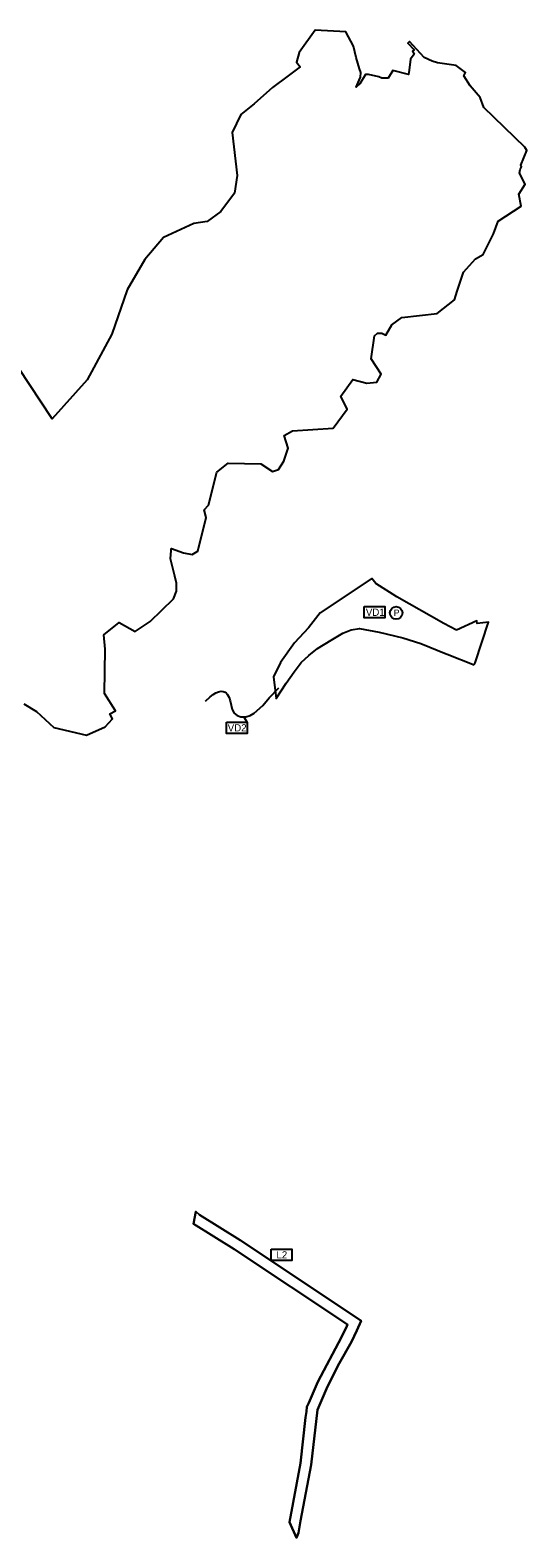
# Model space of a CAD drawing. Extents: x -547623 to -530360, y -1095798 to -1086523.
# Drawn here: x -544764 to -544079, y -1095573 to -1093495 of the extents above; entities that cross this region are included whole.
import ezdxf

# ---------------------------------------------------------------- set-up
doc = ezdxf.new("R2010")
doc.units = 0
for name, color, linetype in [('Vrstva 2', 7, 'Continuous'), ('Vrstva 27', 7, 'Continuous'), ('Vrstva 29', 7, 'Continuous'), ('Vrstva 33', 7, 'Continuous'), ('Vrstva 36', 7, 'Continuous'), ('Vrstva 66', 7, 'Continuous'), ('Vrstva 73', 7, 'Continuous')]:
    doc.layers.add(name, color=color, linetype=linetype)

msp = doc.modelspace()

# ---------------------------------------------------------------- linework, layer by layer
at = {"layer": 'Vrstva 2'}
msp.add_line((-544464.7, -1094448.9), (-544469.2, -1094441.5), dxfattribs=at)
for points in [[(-544303.3, -1094289.4), (-544274.7, -1094289.4), (-544274.7, -1094304.9), (-544303.3, -1094304.9)], [(-544493.3, -1094448.9), (-544464.7, -1094448.9), (-544464.7, -1094464.4), (-544493.3, -1094464.4)]]:
    msp.add_lwpolyline(points, close=True, dxfattribs=at)
at = {"layer": 'Vrstva 27'}
msp.add_lwpolyline([(-544772.6, -1094423.7), (-544755.4, -1094434.1), (-544731.5, -1094456.2), (-544686.3, -1094466.7), (-544660.7, -1094455), (-544650.4, -1094444.2), (-544654, -1094437.3), (-544646.4, -1094433.2), (-544661.7, -1094409.1), (-544660.8, -1094347.9), (-544662.5, -1094328.3), (-544641.1, -1094311.4), (-544619.4, -1094323.8), (-544598.7, -1094310), (-544566.4, -1094278.8), (-544562.2, -1094268.3), (-544562.3, -1094257.2), (-544564.4, -1094247.4), (-544570.5, -1094223.6), (-544569.6, -1094212), (-544569.5, -1094210.6), (-544569.1, -1094209.1), (-544552.5, -1094215.1), (-544540.8, -1094217.7), (-544533.6, -1094213.5), (-544532.8, -1094213.1), (-544521.3, -1094166.5), (-544524, -1094156.1), (-544518.3, -1094149.5), (-544506.4, -1094104.1), (-544491, -1094091.7), (-544446.1, -1094092.6), (-544429.7, -1094103.3), (-544421.7, -1094100.5), (-544414.3, -1094088.9), (-544408.1, -1094071.1), (-544413.8, -1094053.6), (-544402.4, -1094047), (-544346.1, -1094043.3), (-544326.7, -1094017.2), (-544335.8, -1093999.4), (-544319.2, -1093976.5), (-544299.8, -1093981.2), (-544285.8, -1093979.9), (-544280, -1093968.9), (-544293.6, -1093947.9), (-544289.1, -1093916.3), (-544285.1, -1093912.2), (-544279, -1093912.2), (-544273.7, -1093915.3), (-544265.5, -1093900.7), (-544251.4, -1093890.7), (-544202.7, -1093885.2), (-544178.8, -1093866.4), (-544175.4, -1093854.6), (-544166.5, -1093828.2), (-544149.7, -1093810.1), (-544139.3, -1093804.1), (-544125.1, -1093775.4), (-544118.8, -1093757.8), (-544086.8, -1093737.4), (-544090, -1093720.8), (-544081.2, -1093706.9), (-544089, -1093691.9), (-544088.1, -1093686.7), (-544086.5, -1093683.2), (-544087.3, -1093680.9), (-544079.1, -1093660.3), (-544081.8, -1093656), (-544138.2, -1093601.3), (-544143.3, -1093587.3), (-544157.2, -1093571.2), (-544165.8, -1093557.4), (-544163.7, -1093552.9), (-544176.6, -1093543.3), (-544202.3, -1093539.6), (-544209.6, -1093537.3), (-544220.9, -1093532.2), (-544241.1, -1093510.3), (-544243.1, -1093512.6), (-544234.6, -1093521.6), (-544236.7, -1093523.6), (-544234.7, -1093527.8), (-544239.5, -1093534.7), (-544241.4, -1093549.6), (-544242.1, -1093555.6), (-544263.7, -1093550.3), (-544270.3, -1093560.7), (-544279.2, -1093560.9), (-544283.3, -1093558.8), (-544297.5, -1093555.5), (-544301.6, -1093555.8), (-544309.5, -1093568.7), (-544314.3, -1093573.4), (-544310.4, -1093563.7), (-544308.5, -1093559.2), (-544307.9, -1093553.1), (-544309.9, -1093547.8), (-544314.6, -1093532.3), (-544318, -1093516.6), (-544328.6, -1093497.1), (-544371.2, -1093494.6), (-544393.2, -1093525.2), (-544396.8, -1093538.7), (-544391.8, -1093545), (-544408, -1093557.5), (-544429.7, -1093573.7), (-544455.3, -1093596.1), (-544473.6, -1093611), (-544485.4, -1093635.9), (-544478.4, -1093695.1), (-544482.4, -1093719.4), (-544501.3, -1093744.6), (-544519.9, -1093758.4), (-544538.2, -1093761.4), (-544580.2, -1093780.6), (-544605.8, -1093810.6), (-544630.2, -1093852.6), (-544651.5, -1093913.6), (-544685.6, -1093976.9), (-544733.7, -1094030.6), (-544842.2, -1093866.8)], dxfattribs=at)
at = {"layer": 'Vrstva 29'}
for points in [[(-544176.2, -1094322), (-544193.5, -1094312.6), (-544258.4, -1094275.9), (-544287.5, -1094257.8), (-544292.7, -1094250.9), (-544363.9, -1094298), (-544380.2, -1094318.6), (-544399.3, -1094339.3), (-544418.9, -1094366.7), (-544428.6, -1094386.3), (-544424.7, -1094416.2), (-544411.2, -1094395), (-544400, -1094379.3), (-544390.2, -1094366.3), (-544379.7, -1094356.9), (-544367.8, -1094347.3), (-544348.8, -1094335.9), (-544332.8, -1094326.1), (-544321.3, -1094321.4), (-544309.9, -1094319.4), (-544282.7, -1094324.9), (-544250.2, -1094332.4), (-544225.4, -1094340.1), (-544190.5, -1094354.6)], [(-544151.9, -1094369.9), (-544150.3, -1094367), (-544132.1, -1094311.1), (-544147.4, -1094312.7), (-544148, -1094308.9), (-544176.2, -1094322)], [(-544190.5, -1094354.6), (-544189, -1094355.2), (-544151.9, -1094369.9)]]:
    msp.add_lwpolyline(points, dxfattribs=at)
msp.add_circle((-544259.3, -1094298.1), 8.68, dxfattribs=at)
at = {"layer": 'Vrstva 33'}
for points in [[(-544383.1, -1095399.1), (-544382.4, -1095392.8), (-544379.9, -1095387.5), (-544367.4, -1095358.4), (-544334.5, -1095296.6), (-544327.3, -1095281.4), (-544326.4, -1095279.5), (-544482.5, -1095175.5), (-544538.7, -1095140.6), (-544535.6, -1095123.3)], [(-544535.6, -1095123.3), (-544530.3, -1095128.2), (-544474.4, -1095162.9), (-544313.5, -1095270)], [(-544313.5, -1095270), (-544307.4, -1095274.1), (-544313.7, -1095287.8), (-544321.1, -1095303.4), (-544337.7, -1095333.2), (-544353.9, -1095364.9), (-544366.2, -1095393.6)], [(-544366.2, -1095393.6), (-544367.7, -1095396.9), (-544376.6, -1095472.6), (-544391, -1095550), (-544393.9, -1095566.6), (-544396.6, -1095573.5)], [(-544396.6, -1095573.5), (-544406.6, -1095552), (-544391.4, -1095470.4), (-544384.1, -1095407.4)], [(-544384.1, -1095407.4), (-544383.1, -1095399.1)]]:
    msp.add_lwpolyline(points, dxfattribs=at)
at = {"layer": 'Vrstva 36'}
msp.add_lwpolyline([(-544431.9, -1095175.6), (-544403.3, -1095175.6), (-544403.3, -1095191), (-544431.9, -1095191)], close=True, dxfattribs=at)
at = {"layer": 'Vrstva 66'}
msp.add_lwpolyline([(-544522, -1094419.6), (-544515.6, -1094413.9), (-544511.5, -1094410.5), (-544508.2, -1094408.4), (-544504.4, -1094407), (-544500.8, -1094406.2), (-544498, -1094406.4), (-544495.3, -1094407.2), (-544493.6, -1094408.4), (-544492.2, -1094410.1), (-544490.8, -1094412.5), (-544489.8, -1094414.9), (-544488.3, -1094419.4), (-544485.5, -1094431.2), (-544482.8, -1094436.4), (-544478.4, -1094439.4), (-544473.4, -1094441.3), (-544466.5, -1094441.4), (-544460.7, -1094439.8), (-544455.3, -1094436.5), (-544443.3, -1094425.9), (-544434.3, -1094415.3), (-544421.3, -1094401.3)], dxfattribs=at)
at = {"layer": 'Vrstva 73'}
for points in [[(-544772.6, -1094423.7), (-544755.4, -1094434.1), (-544731.5, -1094456.2), (-544686.3, -1094466.7), (-544660.7, -1094455), (-544650.4, -1094444.2), (-544654, -1094437.3), (-544646.4, -1094433.2), (-544661.7, -1094409.1), (-544660.8, -1094347.9), (-544662.5, -1094328.3), (-544641.1, -1094311.4), (-544619.4, -1094323.8), (-544598.7, -1094310), (-544566.4, -1094278.8), (-544562.2, -1094268.3), (-544562.3, -1094257.2), (-544564.4, -1094247.4), (-544570.5, -1094223.6), (-544569.6, -1094212), (-544569.5, -1094210.6), (-544569.1, -1094209.1), (-544552.5, -1094215.1), (-544540.8, -1094217.7), (-544533.6, -1094213.5), (-544532.8, -1094213.1), (-544521.3, -1094166.5), (-544524, -1094156.1), (-544518.3, -1094149.5), (-544506.4, -1094104.1), (-544491, -1094091.7), (-544446.1, -1094092.6), (-544429.7, -1094103.3), (-544421.7, -1094100.5), (-544414.3, -1094088.9), (-544408.1, -1094071.1), (-544413.8, -1094053.6), (-544402.4, -1094047), (-544346.1, -1094043.3), (-544326.7, -1094017.2), (-544335.8, -1093999.4), (-544319.2, -1093976.5), (-544299.8, -1093981.2), (-544285.8, -1093979.9), (-544280, -1093968.9), (-544293.6, -1093947.9), (-544289.1, -1093916.3), (-544285.1, -1093912.2), (-544279, -1093912.2), (-544273.7, -1093915.3), (-544265.5, -1093900.7), (-544251.4, -1093890.7), (-544202.7, -1093885.2), (-544178.8, -1093866.4), (-544175.4, -1093854.6), (-544166.5, -1093828.2), (-544149.7, -1093810.1), (-544139.3, -1093804.1), (-544125.1, -1093775.4), (-544118.8, -1093757.8), (-544086.8, -1093737.4), (-544090, -1093720.8), (-544081.2, -1093706.9), (-544089, -1093691.9), (-544088.1, -1093686.7), (-544086.5, -1093683.2), (-544087.3, -1093680.9), (-544079.1, -1093660.3), (-544081.8, -1093656), (-544138.2, -1093601.3), (-544143.3, -1093587.3), (-544157.2, -1093571.2), (-544165.8, -1093557.4), (-544163.7, -1093552.9), (-544176.6, -1093543.3), (-544202.3, -1093539.6), (-544209.6, -1093537.3), (-544220.9, -1093532.2), (-544241.1, -1093510.3), (-544243.1, -1093512.6), (-544234.6, -1093521.6), (-544236.7, -1093523.6), (-544234.7, -1093527.8), (-544239.5, -1093534.7), (-544241.4, -1093549.6), (-544242.1, -1093555.6), (-544263.7, -1093550.3), (-544270.3, -1093560.7), (-544279.2, -1093560.9), (-544283.3, -1093558.8), (-544297.5, -1093555.5), (-544301.6, -1093555.8), (-544309.5, -1093568.7), (-544314.3, -1093573.4), (-544310.4, -1093563.7), (-544308.5, -1093559.2), (-544307.9, -1093553.1), (-544309.9, -1093547.8), (-544314.6, -1093532.3), (-544318, -1093516.6), (-544328.6, -1093497.1), (-544371.2, -1093494.6), (-544393.2, -1093525.2), (-544396.8, -1093538.7), (-544391.8, -1093545), (-544408, -1093557.5), (-544429.7, -1093573.7), (-544455.3, -1093596.1), (-544473.6, -1093611), (-544485.4, -1093635.9), (-544478.4, -1093695.1), (-544482.4, -1093719.4), (-544501.3, -1093744.6), (-544519.9, -1093758.4), (-544538.2, -1093761.4), (-544580.2, -1093780.6), (-544605.8, -1093810.6), (-544630.2, -1093852.6), (-544651.5, -1093913.6), (-544685.6, -1093976.9), (-544733.7, -1094030.6), (-544842.2, -1093866.8)], [(-544384.1, -1095407.4), (-544391.4, -1095470.4), (-544406.6, -1095552), (-544396.6, -1095573.5), (-544393.9, -1095566.6), (-544391, -1095550), (-544376.6, -1095472.6), (-544367.7, -1095396.9), (-544366.2, -1095393.6), (-544353.9, -1095364.9), (-544337.7, -1095333.2), (-544321.1, -1095303.4), (-544313.7, -1095287.8), (-544307.4, -1095274.1), (-544313.5, -1095270), (-544474.4, -1095162.9), (-544530.3, -1095128.2), (-544535.6, -1095123.3), (-544538.7, -1095140.6), (-544482.5, -1095175.5), (-544326.4, -1095279.5), (-544327.3, -1095281.4), (-544334.5, -1095296.6), (-544367.4, -1095358.4), (-544379.9, -1095387.5), (-544382.4, -1095392.8), (-544383.1, -1095399.1), (-544384.1, -1095407.4)]]:
    msp.add_lwpolyline(points, dxfattribs=at)

# ---------------------------------------------------------------- texts
at = {"layer": 'Vrstva 2'}
for s, p in [('VD1', (-544301.1, -1094302.2)), ('VD2', (-544491.6, -1094461.6))]:
    msp.add_text(s, height=10, dxfattribs=at).set_placement(p)
at = {"layer": 'Vrstva 29'}
msp.add_text('P', height=8.75, dxfattribs=at).set_placement((-544262.6, -1094302.2))
at = {"layer": 'Vrstva 36'}
msp.add_text('L2', height=10, dxfattribs=at).set_placement((-544424.4, -1095188.3))

doc.saveas('drawing.dxf')
